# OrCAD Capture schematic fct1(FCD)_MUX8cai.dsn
size A
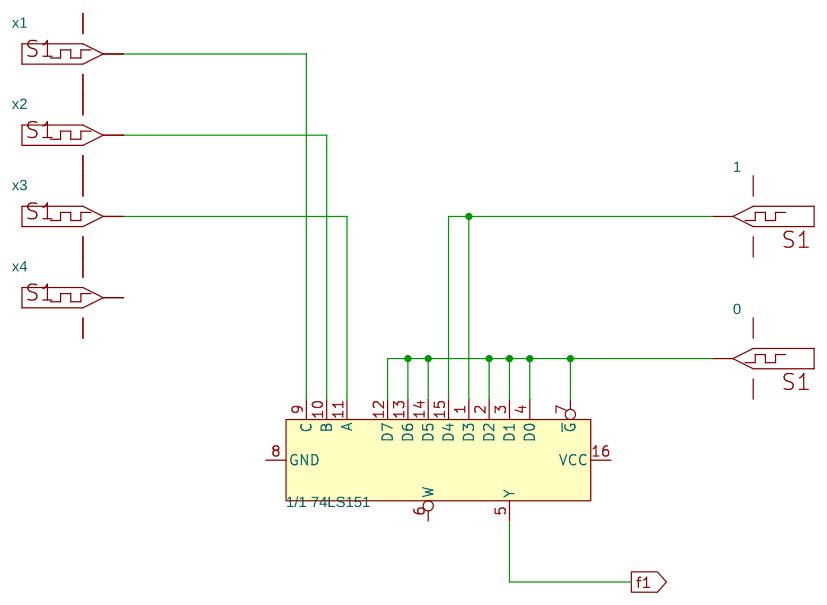
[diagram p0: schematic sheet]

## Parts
0  DigStim1
1  DigStim1
U2  1/1 74LS151  [DIP.100/16/W.300/L.900]
x1  DigStim1
x2  DigStim1
x3  DigStim1
x4  DigStim1

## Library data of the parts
0 1 x1-x4 = DigStim1
U2 = 74LS151

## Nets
GND: 0.3(GND) 1.3(GND) U2.8(GND) x1.3(GND) x2.3(GND) x3.3(GND) x4.3(GND)
VCC: 0.2(VCC) 1.2(VCC) U2.16(VCC) x1.2(VCC) x2.2(VCC) x3.2(VCC) x4.2(VCC)
f1: U2.5(Y)
N14776: 0.OUT U2.2(D2) U2.3(D1) U2.4(D0) U2.7(~{G}) U2.12(D7) U2.13(D6) U2.14(D5)
N15237: 1.OUT U2.1(D3) U2.15(D4)
N15336: U2.9(C) x1.OUT
N15384: U2.10(B) x2.OUT
N15401: U2.11(A) x3.OUT

Not connected (* = marked no-connect by the designer): U2 6(W); x4 OUT
